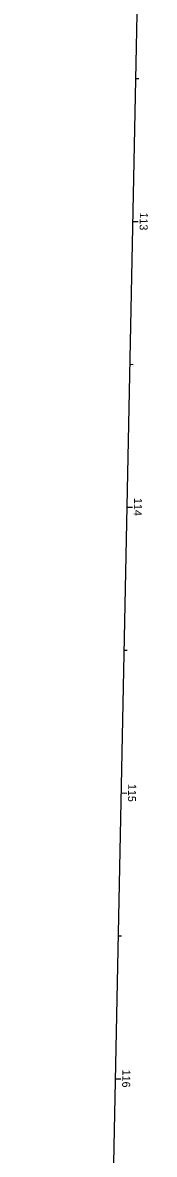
# Model space of a CAD drawing. Extents: x 1392427 to 1392809, y 435950 to 439080.
# Drawn here: x 1392717.3 to 1392763.4, y 437517.5 to 437913.4 of the extents above; entities that cross this region are included whole.
import ezdxf

# ---------------------------------------------------------------- set-up
doc = ezdxf.new("R2010")
doc.units = 0
for name, color, linetype in [('Default', 7, 'Continuous'), ('PV_X_Curb', 7, 'Continuous'), ('RD_X_Cells', 7, 'Continuous'), ('RW_X_CL', 7, 'Continuous'), ('RW_X_CL_100_Stations', 7, 'Continuous'), ('SV_X_Mon_Cells_Found', 7, 'Continuous')]:
    doc.layers.add(name, color=color, linetype=linetype)

msp = doc.modelspace()

# ---------------------------------------------------------------- linework, layer by layer
at = {"layer": 'Default'}
msp.add_line((1392763.4, 438217.67), (1392717.33, 435953.92), dxfattribs=at)
at = {"layer": 'PV_X_Curb'}
for p, q in [((1392755.79, 437843.85), (1392756.99, 437843.83)), ((1392753.76, 437743.87), (1392754.96, 437743.85)), ((1392751.72, 437643.89), (1392753.72, 437643.85)), ((1392749.69, 437543.91), (1392750.89, 437543.89))]:
    msp.add_line(p, q, dxfattribs=at)
at = {"layer": 'RD_X_Cells'}
msp.add_line((1392751.72, 437643.89), (1392752.92, 437643.87), dxfattribs=at)
at = {"layer": 'RW_X_CL'}
msp.add_line((1392763.4, 438217.67), (1392717.33, 435953.92), dxfattribs=at)
msp.add_line((1392763.4, 438217.67), (1392717.33, 435953.92), dxfattribs=at)
at = {"layer": 'RW_X_CL_100_Stations'}
for p, q in [((1392756.81, 437893.84), (1392758.01, 437893.82)), ((1392755.79, 437843.85), (1392757.79, 437843.81)), ((1392754.78, 437793.86), (1392755.98, 437793.84)), ((1392753.76, 437743.87), (1392755.76, 437743.83)), ((1392752.74, 437693.88), (1392753.94, 437693.86)), ((1392751.72, 437643.89), (1392753.72, 437643.85)), ((1392750.71, 437593.9), (1392751.91, 437593.88)), ((1392749.69, 437543.91), (1392751.69, 437543.87))]:
    msp.add_line(p, q, dxfattribs=at)
at = {"layer": 'SV_X_Mon_Cells_Found'}
for p, q in [((1392755.79, 437843.85), (1392756.99, 437843.83)), ((1392753.76, 437743.87), (1392754.96, 437743.85)), ((1392751.72, 437643.89), (1392753.72, 437643.85)), ((1392749.69, 437543.91), (1392750.89, 437543.89))]:
    msp.add_line(p, q, dxfattribs=at)

# ---------------------------------------------------------------- texts
at = {"layer": 'PV_X_Curb'}
msp.add_text('115', height=2.8, rotation=268.834, dxfattribs=at).set_placement((1392754.29, 437647.05))
at = {"layer": 'RW_X_CL_100_Stations'}
for s, p in [('113', (1392758.36, 437847)), ('114', (1392756.32, 437747.1)), ('115', (1392754.29, 437647.05)), ('116', (1392752.25, 437547.12))]:
    msp.add_text(s, height=2.8, rotation=268.834, dxfattribs=at).set_placement(p)
at = {"layer": 'SV_X_Mon_Cells_Found'}
msp.add_text('115', height=2.8, rotation=268.834, dxfattribs=at).set_placement((1392754.29, 437647.05))

doc.saveas('drawing.dxf')
